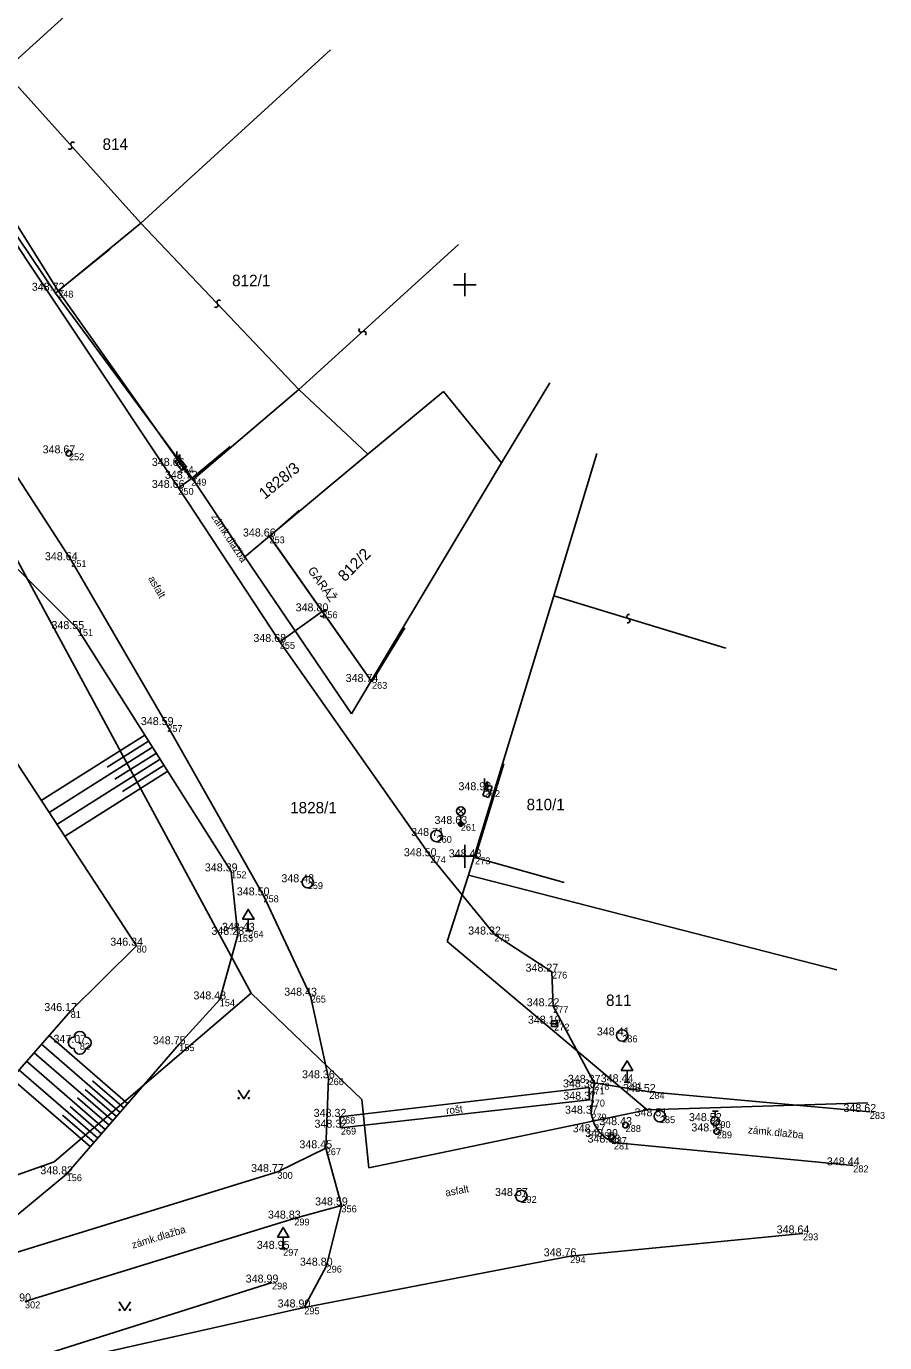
# Model space of a CAD drawing. Extents: x -614046 to -613877, y -1156755 to -1156623.
# Drawn here: x -613935.35 to -613905.3, y -1156717.02 to -1156670.96 of the extents above; entities that cross this region are included whole.
import ezdxf

# ---------------------------------------------------------------- set-up
doc = ezdxf.new("R2010")
doc.units = 0
for name, color, linetype in [('1-bod', 7, 'Continuous'), ('10-silnice', 7, 'Continuous'), ('11-zpevněné plochy', 7, 'Continuous'), ('14-terénní hrany', 7, 'Continuous'), ('15-šrafy', 7, 'Continuous'), ('2-bod výška', 7, 'Continuous'), ('22-stromy', 7, 'Continuous'), ('24-prisky', 7, 'Continuous'), ('27-kanalizace značky', 7, 'Continuous'), ('28-vodovod značky', 7, 'Continuous'), ('3-bod číslo', 7, 'Continuous'), ('33-lampy_závory_rozhlas', 7, 'Continuous'), ('34-dopravní značky', 7, 'Continuous'), ('36-Značky kultur', 7, 'Continuous'), ('40-popisy povrchů', 7, 'Continuous'), ('41-Popis objektů', 7, 'Continuous'), ('5-budova', 7, 'Continuous'), ('50-hranice parcel KN', 7, 'Continuous'), ('61-hektarová síť', 7, 'Continuous'), ('7-plot', 7, 'Continuous'), ('9-zábradlí svodidlo', 7, 'Continuous')]:
    doc.layers.add(name, color=color, linetype=linetype)

# ---------------------------------------------------------------- blocks, each defined once
blk = doc.blocks.new('6.20_1')
at = {"layer": '27-kanalizace značky'}
blk.add_circle((0, 0), 0.5, dxfattribs=at)
blk = doc.blocks.new('6.14A_1')
at = {"layer": '28-vodovod značky'}
blk.add_circle((0, 0), 0.25, dxfattribs=at)
blk = doc.blocks.new('6.13_1')
at = {"layer": '28-vodovod značky'}
for p, q in [((-0.26, -0.27), (0.27, 0.26)), ((-0.25, 0.88), (0.25, 0.88)), ((0, 0.38), (0, 0.88))]:
    blk.add_line(p, q, dxfattribs=at)
blk.add_circle((0, 0), 0.375, dxfattribs=at)
blk = doc.blocks.new('5.270')
at = {"layer": '34-dopravní značky'}
for p, q in [((-0.25, 0), (0.25, 0)), ((0, 1.02), (0, 0))]:
    blk.add_line(p, q, dxfattribs=at)
blk.add_lwpolyline([(-0.5, 1.02), (0.5, 1.02), (0, 1.88)], close=True, dxfattribs=at)
blk = doc.blocks.new('6.30')
at = {"layer": '27-kanalizace značky'}
blk.add_line((-0.25, 0), (0.25, 0), dxfattribs=at)
blk.add_lwpolyline([(-0.25, -0.25), (0.25, -0.25), (0.25, 0.25), (-0.25, 0.25)], close=True, dxfattribs=at)
blk = doc.blocks.new('3.13_1')
at = {"layer": '22-stromy'}
blk.add_circle((0, 0), 0.05, dxfattribs=at)
for centre, start, end in [((-0.5, 0), 90, 270), ((0, 0.5), 0, 180), ((0.5, 0), 270, 90), ((0, -0.5), 180, 0)]:
    blk.add_arc(centre, 0.5, start, end, dxfattribs=at)
blk = doc.blocks.new('6.560_1')
at = {"layer": '33-lampy_závory_rozhlas'}
for p, q in [((-0.26, 0.86), (0.26, 1.39)), ((-0.26, 1.39), (0.26, 0.86)), ((0, 0.75), (0, 0))]:
    blk.add_line(p, q, dxfattribs=at)
for centre, radius in [((0, 1.12), 0.375), ((0, 0), 0.2), ((0, 0), 0.145), ((0, 0), 0.0876)]:
    blk.add_circle(centre, radius, dxfattribs=at)
blk = doc.blocks.new('3.14')
at = {"layer": '36-Značky kultur'}
blk.add_lwpolyline([(-0.5, 0.75), (0, 0), (0.5, 0.75)], dxfattribs=at)
for centre in [(-0.45, 0.05), (0.45, 0.05)]:
    blk.add_circle(centre, 0.05, dxfattribs=at)
blk = doc.blocks.new('6.66_1')
at = {"layer": '24-prisky'}
for p, q in [((0.5, 0.5), (-0.5, 0.5)), ((-0.5, 0.5), (-0.5, 0)), ((0.5, 0), (0.5, 0.5)), ((-0.5, 0), (0.5, 0))]:
    blk.add_line(p, q, dxfattribs=at)
blk = doc.blocks.new('PE_1')
at = {"layer": '24-prisky'}
for p, q in [((-0.25, 1.13), (-0.25, 0.5)), ((-0.25, 0.5), (0, 0.88)), ((-0.11, 0.25), (0, 0)), ((0, 0.88), (0, 0)), ((0, 0), (0.11, 0.25))]:
    blk.add_line(p, q, dxfattribs=at)
blk = doc.blocks.new('2.18')
at = {"layer": '50-hranice parcel KN'}
for centre, start, end in [((0, 0.19), 90, 270), ((0, -0.19), 270, 90)]:
    blk.add_arc(centre, 0.187, start, end, dxfattribs=at)
blk = doc.blocks.new('POINT_DISPLAY')
blk.add_line((0, 0), (0, 0))

msp = doc.modelspace()

# ---------------------------------------------------------------- linework, layer by layer
at = {"layer": '10-silnice'}
for points in [[(-613960.9, -1156628.99), (-613958.35, -1156634.24), (-613954.84, -1156641.03), (-613949.45, -1156651.67), (-613945.11, -1156660.46), (-613942.99, -1156664.94), (-613940.24, -1156671.03), (-613939.6, -1156670.78), (-613938.01, -1156674.2), (-613937.19, -1156675.55), (-613937.22, -1156676.32), (-613930.03, -1156687.11), (-613926.48, -1156692.5), (-613921.2, -1156700), (-613918.96, -1156702.74), (-613916.95, -1156704.04), (-613916.91, -1156705.25), (-613915.47, -1156707.93), (-613915.57, -1156709.01), (-613915.47, -1156709.37), (-613915.3, -1156709.66), (-613915.08, -1156709.85), (-613914.78, -1156710.02), (-613906.4, -1156710.82)], [(-613937.12, -1156718.51), (-613933.57, -1156717.58), (-613925.62, -1156715.79), (-613924.84, -1156714.33), (-613924.32, -1156712.22), (-613924.87, -1156710.22), (-613924.77, -1156707.77), (-613925.4, -1156704.88), (-613927.05, -1156701.37), (-613930.42, -1156695.41), (-613933.78, -1156689.64), (-613939.48, -1156680.87), (-613941.35, -1156679.26), (-613943.8, -1156674.41), (-613943.3, -1156673.71), (-613943.36, -1156673.41), (-613946.37, -1156666.81), (-613948.28, -1156662.1), (-613952.52, -1156653.05)], [(-613925.62, -1156715.79), (-613916.31, -1156714), (-613908.16, -1156713.2)]]:
    msp.add_lwpolyline(points, dxfattribs=at)
at = {"layer": '11-zpevněné plochy'}
for p, q in [((-613924.99, -1156691.43), (-613926.48, -1156692.5)), ((-613915.47, -1156707.93), (-613913.54, -1156708.25)), ((-613924.37, -1156709.12), (-613915.64, -1156708.09)), ((-613915.64, -1156708.09), (-613915.63, -1156708.52)), ((-613913.54, -1156708.25), (-613905.82, -1156708.95)), ((-613915.63, -1156708.52), (-613924.34, -1156709.5)), ((-613924.34, -1156709.5), (-613924.37, -1156709.12)), ((-613926.56, -1156711.05), (-613924.87, -1156710.22)), ((-613935.9, -1156713.93), (-613926.56, -1156711.05)), ((-613925.97, -1156712.68), (-613924.32, -1156712.22)), ((-613935.4, -1156715.58), (-613925.97, -1156712.68))]:
    msp.add_line(p, q, dxfattribs=at)
msp.add_lwpolyline([(-613930.03, -1156687.11), (-613929.58, -1156686.79)], dxfattribs=at)
at = {"layer": '14-terénní hrany'}
for points in [[(-613940.16, -1156716.75), (-613937.91, -1156714.4), (-613933.94, -1156711.13), (-613930, -1156706.58), (-613928.58, -1156705.01), (-613927.95, -1156702.75), (-613928.18, -1156700.53), (-613933.55, -1156692.05), (-613939.5, -1156686.1), (-613943.86, -1156682.78), (-613948.89, -1156677.3), (-613953.73, -1156674.72)], [(-613951.83, -1156677.12), (-613952.88, -1156678.6), (-613948.44, -1156684.71), (-613942.44, -1156689.03), (-613937.52, -1156693.96), (-613931.49, -1156703.13), (-613933.8, -1156705.42), (-613937.38, -1156709.49), (-613940.48, -1156713.13)]]:
    msp.add_lwpolyline(points, dxfattribs=at)
at = {"layer": '15-šrafy'}
for p, q in [((-613931.2, -1156695.76), (-613934.83, -1156698.05)), ((-613930.94, -1156696.18), (-613934.55, -1156698.47)), ((-613931.07, -1156695.97), (-613932.52, -1156696.88)), ((-613930.8, -1156696.39), (-613932.25, -1156697.3)), ((-613930.67, -1156696.6), (-613934.28, -1156698.89)), ((-613930.53, -1156696.81), (-613931.98, -1156697.73)), ((-613930.4, -1156697.02), (-613934.01, -1156699.31)), ((-613931.801, -1156708.659), (-613934.553, -1156706.276)), ((-613932.324, -1156709.264), (-613935.081, -1156706.877)), ((-613932.062, -1156708.962), (-613934.817, -1156706.576)), ((-613932.848, -1156709.869), (-613935.61, -1156707.477)), ((-613932.586, -1156709.567), (-613935.346, -1156707.177)), ((-613933.11, -1156710.171), (-613935.874, -1156707.778)), ((-613931.932, -1156708.811), (-613933.033, -1156707.857)), ((-613932.193, -1156709.113), (-613933.296, -1156708.158)), ((-613932.717, -1156709.718), (-613933.821, -1156708.762)), ((-613932.455, -1156709.415), (-613933.558, -1156708.46)), ((-613932.979, -1156710.02), (-613934.084, -1156709.063))]:
    msp.add_line(p, q, dxfattribs=at)
at = {"layer": '5-budova'}
for p, q in [((-613923.25, -1156693.9), (-613926.84, -1156688.81)), ((-613919.64, -1156700.04), (-613918.63, -1156696.76)), ((-613919.64, -1156700.04), (-613916.52, -1156700.92))]:
    msp.add_line(p, q, dxfattribs=at)
for points in [[(-613926.84, -1156688.81), (-613925.8, -1156687.9)], [(-613923.25, -1156693.9), (-613922.1, -1156692.01)]]:
    msp.add_lwpolyline(points, dxfattribs=at)
at = {"layer": '50-hranice parcel KN'}
for p, q in [((-613924.697, -1156671.775), (-613931.34, -1156677.84)), ((-613934.33, -1156680.29), (-613929.51, -1156686.81)), ((-613917.022, -1156683.427), (-613918.71, -1156686.23)), ((-613929.51, -1156686.81), (-613925.81, -1156683.67)), ((-613915.382, -1156685.9), (-613916.88, -1156690.89)), ((-613929.51, -1156686.81), (-613927.7, -1156689.52)), ((-613919.87, -1156700.66), (-613916.88, -1156690.89)), ((-613910.858, -1156692.723), (-613916.88, -1156690.89)), ((-613923.28, -1156693.86), (-613923.97, -1156695.02))]:
    msp.add_line(p, q, dxfattribs=at)
for points in [[(-613936.13, -1156672.52), (-613930.87, -1156667.74)], [(-613931.34, -1156677.84), (-613936.13, -1156672.52)], [(-613936.96, -1156676.41), (-613934.33, -1156680.29)], [(-613931.34, -1156677.84), (-613934.33, -1156680.29)], [(-613925.81, -1156683.67), (-613931.34, -1156677.84)], [(-613925.81, -1156683.67), (-613920.217, -1156678.593)], [(-613939.01, -1156683.48), (-613927.48, -1156704.79)], [(-613925.81, -1156683.67), (-613923.39, -1156685.93)], [(-613923.39, -1156685.93), (-613920.75, -1156683.74)], [(-613920.75, -1156683.74), (-613918.71, -1156686.23)], [(-613923.39, -1156685.93), (-613926.84, -1156688.8)], [(-613918.71, -1156686.23), (-613923.28, -1156693.86)], [(-613926.84, -1156688.8), (-613927.7, -1156689.52)], [(-613926.84, -1156688.8), (-613923.28, -1156693.86)], [(-613927.7, -1156689.52), (-613923.97, -1156695.02)], [(-613920.62, -1156702.98), (-613919.87, -1156700.66)], [(-613919.87, -1156700.66), (-613906.973, -1156703.971)], [(-613913.62, -1156708.88), (-613920.62, -1156702.98)], [(-613927.48, -1156704.79), (-613934.38, -1156710.7)], [(-613923.6, -1156708.51), (-613927.48, -1156704.79)], [(-613923.36, -1156710.91), (-613923.6, -1156708.51)], [(-613905.893, -1156708.634), (-613913.62, -1156708.88)], [(-613913.62, -1156708.88), (-613923.36, -1156710.91)], [(-613934.38, -1156710.7), (-613937.06, -1156711.64)]]:
    msp.add_lwpolyline(points, dxfattribs=at)
at = {"layer": '61-hektarová síť'}
for points in [[(-613920, -1156680.4), (-613920, -1156680), (-613920, -1156679.6)], [(-613920.4, -1156680), (-613920, -1156680), (-613919.6, -1156680)], [(-613920, -1156700.4), (-613920, -1156700), (-613920, -1156699.6)], [(-613920.4, -1156700), (-613920, -1156700), (-613919.6, -1156700)]]:
    msp.add_lwpolyline(points, dxfattribs=at)
at = {"layer": '7-plot'}
msp.add_line((-613932.425, -1156678.756), (-613934.24, -1156680.21), dxfattribs=at)
for points in [[(-613934.24, -1156680.21), (-613938.01, -1156674.2), (-613936.81, -1156673.13)], [(-613928.21, -1156685.664), (-613929.58, -1156686.79), (-613934.24, -1156680.21)]]:
    msp.add_lwpolyline(points, dxfattribs=at)
at = {"layer": '9-zábradlí svodidlo'}
msp.add_lwpolyline([(-613926.75, -1156714.92), (-613959.84, -1156725.38), (-613967.42, -1156727.38), (-613969.94, -1156727.63), (-613973.07, -1156727.23), (-613976.34, -1156725.86), (-613978.17, -1156724.15)], dxfattribs=at)

# ---------------------------------------------------------------- block references
at = {"layer": '1-bod'}
for p in [(-613934.24, -1156680.21), (-613933.86, -1156685.9), (-613930.03, -1156686.34), (-613930.03, -1156687.11), (-613929.58, -1156686.79), (-613926.84, -1156688.81), (-613933.78, -1156689.64), (-613924.99, -1156691.43), (-613933.55, -1156692.05), (-613926.48, -1156692.5), (-613923.25, -1156693.9), (-613930.42, -1156695.41), (-613919.3, -1156697.69), (-613920.14, -1156698.87), (-613920.99, -1156699.29), (-613921.2, -1156700), (-613919.64, -1156700.04), (-613928.18, -1156700.53), (-613925.5, -1156700.91), (-613927.05, -1156701.37), (-613927.95, -1156702.75), (-613927.58, -1156702.61), (-613918.96, -1156702.74), (-613931.49, -1156703.13), (-613916.95, -1156704.04), (-613928.58, -1156705.01), (-613925.4, -1156704.88), (-613933.8, -1156705.42), (-613916.91, -1156705.25), (-613916.87, -1156705.86), (-613933.48, -1156706.53), (-613914.49, -1156706.27), (-613930, -1156706.58), (-613924.77, -1156707.77), (-613915.47, -1156707.93), (-613914.32, -1156707.91), (-613915.64, -1156708.09), (-613913.54, -1156708.25), (-613915.63, -1156708.52), (-613924.37, -1156709.12), (-613915.57, -1156709.01), (-613913.17, -1156709.1), (-613911.23, -1156709.27), (-613905.82, -1156708.95), (-613924.34, -1156709.5), (-613915.3, -1156709.66), (-613914.37, -1156709.41), (-613911.18, -1156709.63), (-613924.87, -1156710.22), (-613914.86, -1156709.83), (-613914.78, -1156710.02), (-613933.94, -1156711.13), (-613926.56, -1156711.05), (-613906.4, -1156710.82), (-613918.02, -1156711.89), (-613924.32, -1156712.22), (-613925.97, -1156712.68), (-613908.16, -1156713.2), (-613926.36, -1156713.74), (-613924.84, -1156714.33), (-613916.31, -1156714), (-613926.75, -1156714.92), (-613925.62, -1156715.79)]:
    msp.add_blockref('POINT_DISPLAY', p, dxfattribs=at)
at = {"layer": '22-stromy', "xscale": 0.4, "yscale": 0.4000000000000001}
msp.add_blockref('3.13_1', (-613933.48, -1156706.53), dxfattribs=at)
at = {"layer": '24-prisky', "xscale": 0.4}
for p, yscale, rotation in [((-613930.03, -1156686.34), 0.4000000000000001, -51.75905537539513), ((-613919.3, -1156697.69), 0.39999999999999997, -108.66443937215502)]:
    msp.add_blockref('6.66_1', p, dxfattribs=dict(at, yscale=yscale, rotation=rotation))
at = {"layer": '24-prisky', "xscale": 0.4, "yscale": 0.4000000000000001}
for p in [(-613929.978, -1156686.293), (-613919.211, -1156697.736)]:
    msp.add_blockref('PE_1', p, dxfattribs=at)
at = {"layer": '27-kanalizace značky', "xscale": 0.4, "yscale": 0.4000000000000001}
for name, p in [('6.20_1', (-613920.99, -1156699.29)), ('6.20_1', (-613925.5, -1156700.91)), ('6.30', (-613916.87, -1156705.86)), ('6.20_1', (-613914.49, -1156706.27)), ('6.20_1', (-613913.17, -1156709.1)), ('6.20_1', (-613918.02, -1156711.89))]:
    msp.add_blockref(name, p, dxfattribs=at)
at = {"layer": '28-vodovod značky', "xscale": 0.4, "yscale": 0.4000000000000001}
for name, p in [('6.14A_1', (-613933.86, -1156685.9)), ('6.14A_1', (-613914.37, -1156709.41)), ('6.13_1', (-613911.23, -1156709.27)), ('6.14A_1', (-613914.86, -1156709.83)), ('6.14A_1', (-613911.18, -1156709.63))]:
    msp.add_blockref(name, p, dxfattribs=at)
at = {"layer": '33-lampy_závory_rozhlas', "xscale": 0.4, "yscale": 0.4000000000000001}
msp.add_blockref('6.560_1', (-613920.14, -1156698.87), dxfattribs=at)
at = {"layer": '34-dopravní značky', "xscale": 0.4, "yscale": 0.4000000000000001}
for p in [(-613927.58, -1156702.61), (-613914.32, -1156707.91), (-613926.36, -1156713.74)]:
    msp.add_blockref('5.270', p, dxfattribs=at)
at = {"layer": '36-Značky kultur', "xscale": 0.4, "yscale": 0.4000000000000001}
for p in [(-613927.74, -1156708.485), (-613931.904, -1156715.892)]:
    msp.add_blockref('3.14', p, dxfattribs=at)
at = {"layer": '50-hranice parcel KN'}
for p, xscale, yscale, rotation in [((-613933.779, -1156675.132), 0.39999999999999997, 0.40000000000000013, -48.00088931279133), ((-613928.66, -1156680.665), 0.39999999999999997, 0.39999999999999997, 133.48725880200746), ((-613923.581, -1156681.647), 0.39999999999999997, 0.39999999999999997, -137.7702157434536), ((-613924.943, -1156691.496), 0.39999999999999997, 0.3999999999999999, 125.12857801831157), ((-613914.273, -1156691.684), 0.4, 0.4000000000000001, 163.07248690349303)]:
    msp.add_blockref('2.18', p, dxfattribs=dict(at, xscale=xscale, yscale=yscale, rotation=rotation))

# ---------------------------------------------------------------- texts
at = {"layer": '2-bod výška'}
for s, p in [('348.72 ', (-613935.162, -1156680.21)), ('348.67 ', (-613934.782, -1156685.9)), ('348.66 ', (-613930.958, -1156686.34)), ('348.72 ', (-613930.502, -1156686.79)), ('348.66 ', (-613930.958, -1156687.11)), ('348.66 ', (-613927.768, -1156688.81)), ('348.64 ', (-613934.702, -1156689.64)), ('348.80 ', (-613925.923, -1156691.43)), ('348.55 ', (-613934.472, -1156692.05)), ('348.68 ', (-613927.402, -1156692.5)), ('348.74 ', (-613924.172, -1156693.9)), ('348.59 ', (-613931.342, -1156695.41)), ('348.92 ', (-613920.222, -1156697.69)), ('348.63 ', (-613921.062, -1156698.87)), ('348.71 ', (-613921.877, -1156699.29)), ('348.50 ', (-613922.133, -1156700)), ('348.48 ', (-613920.562, -1156700.04)), ('348.39 ', (-613929.102, -1156700.53)), ('348.48 ', (-613926.422, -1156700.91)), ('348.50 ', (-613927.983, -1156701.37)), ('348.43 ', (-613928.502, -1156702.61)), ('346.34 ', (-613932.412, -1156703.13)), ('348.28 ', (-613928.872, -1156702.75)), ('348.32 ', (-613919.882, -1156702.74)), ('348.27 ', (-613917.872, -1156704.04)), ('348.43 ', (-613926.322, -1156704.88)), ('346.17 ', (-613934.722, -1156705.42)), ('348.48 ', (-613929.502, -1156705.01)), ('348.22 ', (-613917.832, -1156705.25)), ('348.19 ', (-613917.792, -1156705.86)), ('348.41 ', (-613915.377, -1156706.27)), ('347.07 ', (-613934.402, -1156706.53)), ('348.75 ', (-613930.922, -1156706.58)), ('348.36 ', (-613925.698, -1156707.77)), ('348.38 ', (-613916.562, -1156708.09)), ('348.37 ', (-613916.392, -1156707.93)), ('348.44 ', (-613915.242, -1156707.91)), ('348.37 ', (-613916.552, -1156708.52)), ('348.52 ', (-613914.462, -1156708.25)), ('348.32 ', (-613925.292, -1156709.12)), ('348.37 ', (-613916.492, -1156709.01)), ('348.51 ', (-613914.057, -1156709.1)), ('348.62 ', (-613906.742, -1156708.95)), ('348.32 ', (-613925.262, -1156709.5)), ('348.43 ', (-613915.292, -1156709.41)), ('348.52 ', (-613912.152, -1156709.27)), ('348.37 ', (-613916.222, -1156709.66)), ('348.39 ', (-613915.782, -1156709.83)), ('348.38 ', (-613915.702, -1156710.02)), ('348.51 ', (-613912.067, -1156709.63)), ('348.45 ', (-613925.792, -1156710.22)), ('348.44 ', (-613907.322, -1156710.82)), ('348.82 ', (-613934.862, -1156711.13)), ('348.77 ', (-613927.482, -1156711.05)), ('348.57 ', (-613918.942, -1156711.89)), ('348.59 ', (-613925.242, -1156712.22)), ('348.83 ', (-613926.892, -1156712.68)), ('348.64 ', (-613909.082, -1156713.2)), ('348.95 ', (-613927.282, -1156713.74)), ('348.76 ', (-613917.238, -1156714)), ('348.80 ', (-613925.773, -1156714.33)), ('348.99 ', (-613927.672, -1156714.92)), ('348.90 ', (-613936.333, -1156715.58)), ('348.90 ', (-613926.553, -1156715.79))]:
    msp.add_text(s, height=0.28, dxfattribs=at).set_placement(p)
at = {"layer": '3-bod číslo'}
for s, p in [('248', (-613934.24, -1156680.45)), ('252', (-613933.86, -1156686.14)), ('254', (-613930.03, -1156686.58)), ('250', (-613930.03, -1156687.35)), ('249', (-613929.58, -1156687.03)), ('253', (-613926.84, -1156689.05)), ('251', (-613933.78, -1156689.88)), ('256', (-613924.99, -1156691.67)), ('151', (-613933.55, -1156692.29)), ('255', (-613926.48, -1156692.74)), ('263', (-613923.25, -1156694.14)), ('257', (-613930.42, -1156695.65)), ('262', (-613919.3, -1156697.93)), ('261', (-613920.14, -1156699.11)), ('260', (-613920.99, -1156699.53)), ('274', (-613921.2, -1156700.24)), ('273', (-613919.64, -1156700.28)), ('152', (-613928.18, -1156700.77)), ('259', (-613925.5, -1156701.15)), ('258', (-613927.05, -1156701.61)), ('153', (-613927.95, -1156702.99)), ('264', (-613927.58, -1156702.85)), ('275', (-613918.96, -1156702.98)), ('80', (-613931.49, -1156703.37)), ('276', (-613916.95, -1156704.28)), ('154', (-613928.58, -1156705.25)), ('265', (-613925.4, -1156705.12)), ('81', (-613933.8, -1156705.66)), ('277', (-613916.91, -1156705.49)), ('272', (-613916.87, -1156706.1)), ('82', (-613933.48, -1156706.77)), ('286', (-613914.49, -1156706.51)), ('155', (-613930, -1156706.82)), ('266', (-613924.77, -1156708.01)), ('278', (-613915.47, -1156708.17)), ('291', (-613914.32, -1156708.15)), ('271', (-613915.64, -1156708.33)), ('284', (-613913.54, -1156708.49)), ('270', (-613915.63, -1156708.76)), ('268', (-613924.37, -1156709.36)), ('279', (-613915.57, -1156709.25)), ('285', (-613913.17, -1156709.34)), ('290', (-613911.23, -1156709.51)), ('283', (-613905.82, -1156709.19)), ('269', (-613924.34, -1156709.74)), ('280', (-613915.3, -1156709.9)), ('288', (-613914.37, -1156709.65)), ('289', (-613911.18, -1156709.87)), ('267', (-613924.87, -1156710.46)), ('287', (-613914.86, -1156710.07)), ('281', (-613914.78, -1156710.26)), ('156', (-613933.94, -1156711.37)), ('300', (-613926.56, -1156711.29)), ('282', (-613906.4, -1156711.06)), ('292', (-613918.02, -1156712.13)), ('356', (-613924.32, -1156712.46)), ('299', (-613925.97, -1156712.92)), ('293', (-613908.16, -1156713.44)), ('297', (-613926.36, -1156713.98)), ('296', (-613924.84, -1156714.57)), ('294', (-613916.31, -1156714.24)), ('298', (-613926.75, -1156715.16)), ('302', (-613935.4, -1156715.82)), ('295', (-613925.62, -1156716.03))]:
    msp.add_text(s, height=0.24, dxfattribs=at).set_placement(p)
at = {"layer": '40-popisy povrchů'}
for s, rotation, p in [('zámk.dlažba', 303.37, (-613928.89, -1156688.114)), ('asfalt', 300.2132, (-613931.098, -1156690.28)), ('rošt', 6.7289, (-613920.64, -1156709.03)), ('zámk.dlažba', 354.5468, (-613910.096, -1156709.696)), ('asfalt', 10.8832, (-613920.659, -1156711.909)), ('zámk.dlažba', 17.0942, (-613931.619, -1156713.735))]:
    msp.add_text(s, height=0.26, rotation=rotation, dxfattribs=at).set_placement(p)
at = {"layer": '41-Popis objektů'}
msp.add_text('GARÁŽ', height=0.3, rotation=305.1955, dxfattribs=at).set_placement((-613925.512, -1156689.998))
at = {"layer": '50-hranice parcel KN'}
for s, p in [('814', (-613932.684, -1156675.28)), ('812/1', (-613928.148, -1156680.05)), ('1828/1', (-613926.116, -1156698.5)), ('810/1', (-613917.837, -1156698.39)), ('811', (-613915.055, -1156705.24))]:
    msp.add_text(s, height=0.4, dxfattribs=at).set_placement(p)
for s, rotation, p in [('1828/3', 39.5362, (-613927.004, -1156687.527)), ('812/2', 45.5989, (-613924.199, -1156690.416))]:
    msp.add_text(s, height=0.4, rotation=rotation, dxfattribs=at).set_placement(p)

doc.saveas('drawing.dxf')
